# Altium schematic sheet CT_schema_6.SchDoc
size 387 x 379 mm
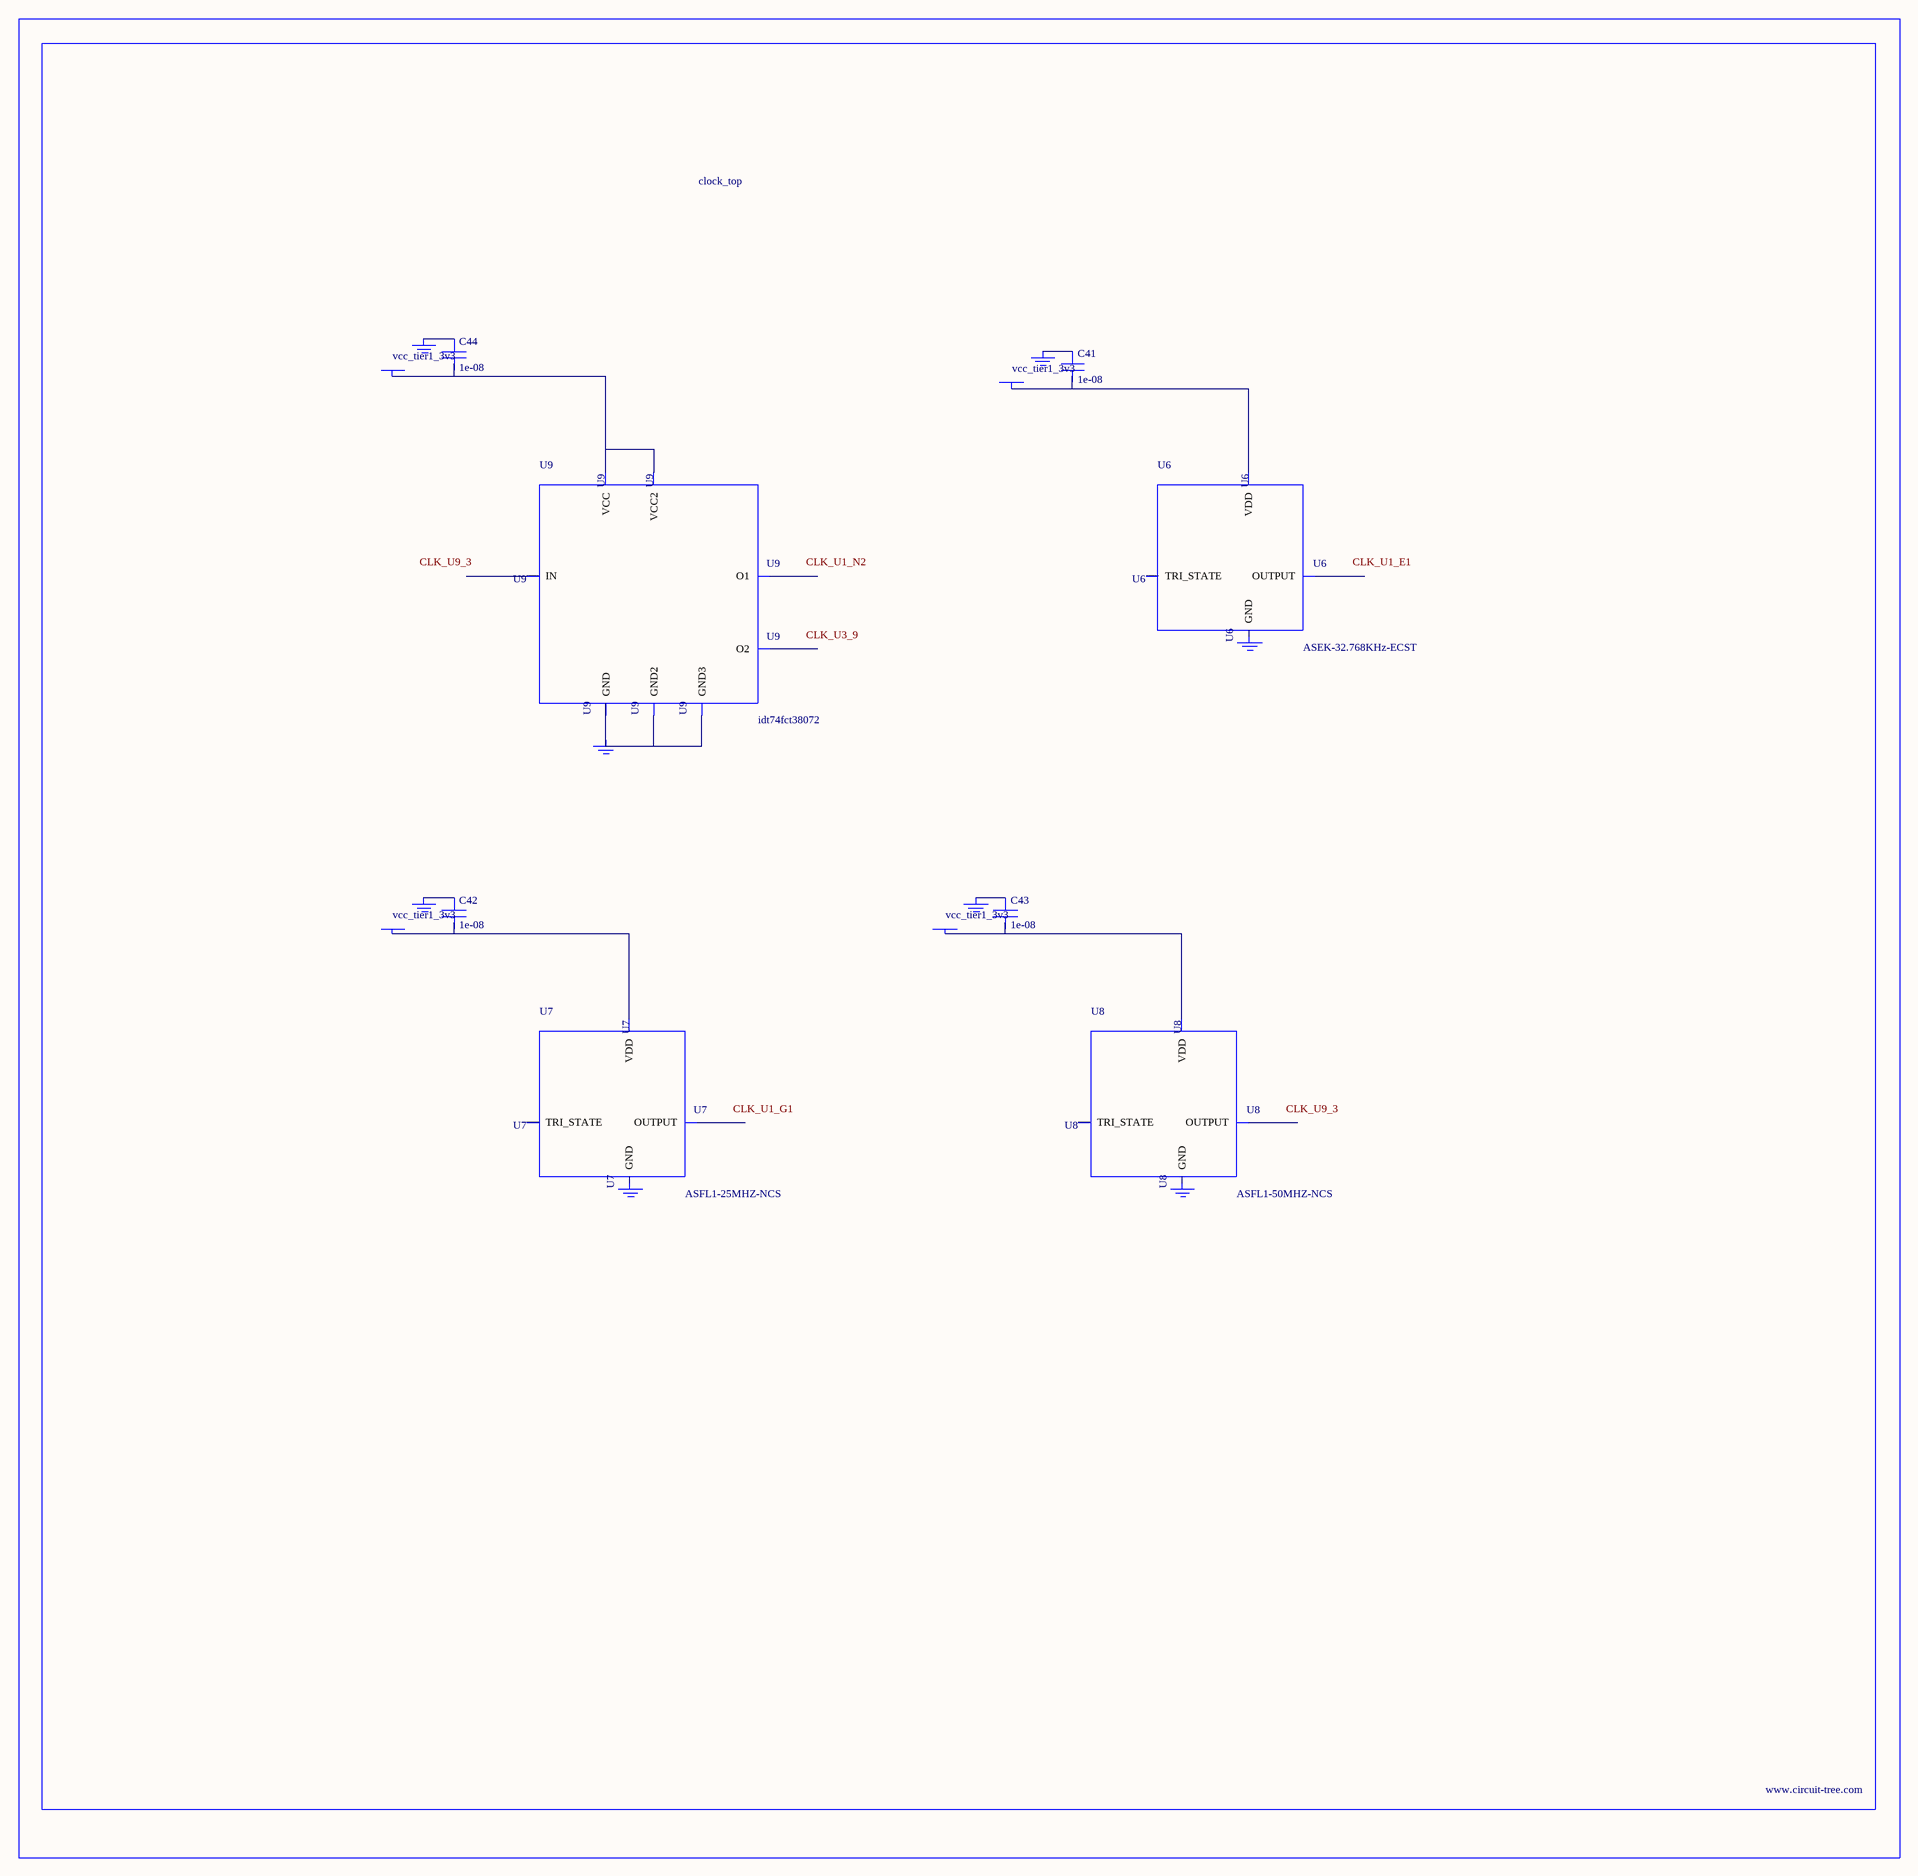
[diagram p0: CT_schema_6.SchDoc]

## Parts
BORDER5  (no value)
C41  1e-08  [C0402]
C42  1e-08  [C0402]
C43  1e-08  [C0402]
C44  1e-08  [C0402]
GND_INSTANCE_5_0  (no value)
GND_INSTANCE_5_1  (no value)
GND_INSTANCE_5_2  (no value)
GND_INSTANCE_5_3  (no value)
GND_INSTANCE_5_4  (no value)
GND_INSTANCE_5_5  (no value)
GND_INSTANCE_5_6  (no value)
GND_INSTANCE_5_7  (no value)
POWER_INSTANCE_5_0  vcc_tier1_3v3
POWER_INSTANCE_5_1  vcc_tier1_3v3
POWER_INSTANCE_5_2  vcc_tier1_3v3
POWER_INSTANCE_5_3  vcc_tier1_3v3
U6  ASEK-32.768KHz-ECST  [ASEK]
U7  ASFL1-25MHZ-NCS  [ASFL1]
U8  ASFL1-50MHZ-NCS  [ASFL1]
U9  idt74fct38072  [IDT74FCT38072]

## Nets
NetC41_1: C41.1 GND_INSTANCE_5_0.0(GND)
NetC41_2: C41.2 POWER_INSTANCE_5_0.0(PWR) U6.4(VDD)
NetC42_1: C42.1 GND_INSTANCE_5_2.0(GND)
NetC42_2: C42.2 POWER_INSTANCE_5_1.0(PWR) U7.4(VDD)
NetC43_1: C43.1 GND_INSTANCE_5_4.0(GND)
NetC43_2: C43.2 POWER_INSTANCE_5_2.0(PWR) U8.4(VDD)
NetC44_1: C44.1 GND_INSTANCE_5_6.0(GND)
NetC44_2: C44.2 POWER_INSTANCE_5_3.0(PWR) U9.1(VCC) U9.2(VCC2)
NetGND_INSTANCE_5_7_0: GND_INSTANCE_5_7.0(GND) U9.4(GND) U9.5(GND2) U9.8(GND3)

Not connected (* = marked no-connect by the designer): GND_INSTANCE_5_1 0(GND); GND_INSTANCE_5_3 0(GND); GND_INSTANCE_5_5 0(GND); U6 1(TRI_STATE) 2(GND) 3(OUTPUT); U7 1(TRI_STATE) 2(GND) 3(OUTPUT); U8 1(TRI_STATE) 2(GND) 3(OUTPUT); U9 3(IN) 6(O2) 7(O1)

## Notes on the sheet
- Labels drawn without touching a wire or pin: CLK_U1_E1, CLK_U1_G1, CLK_U1_N2, CLK_U3_9, CLK_U9_3

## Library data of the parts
BORDER5 = BORDER_PAGE5
C41-C44 = C0402C103K3RAC
GND_INSTANCE_5_0-GND_INSTANCE_5_7 = GND
POWER_INSTANCE_5_0-POWER_INSTANCE_5_3 = PWR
